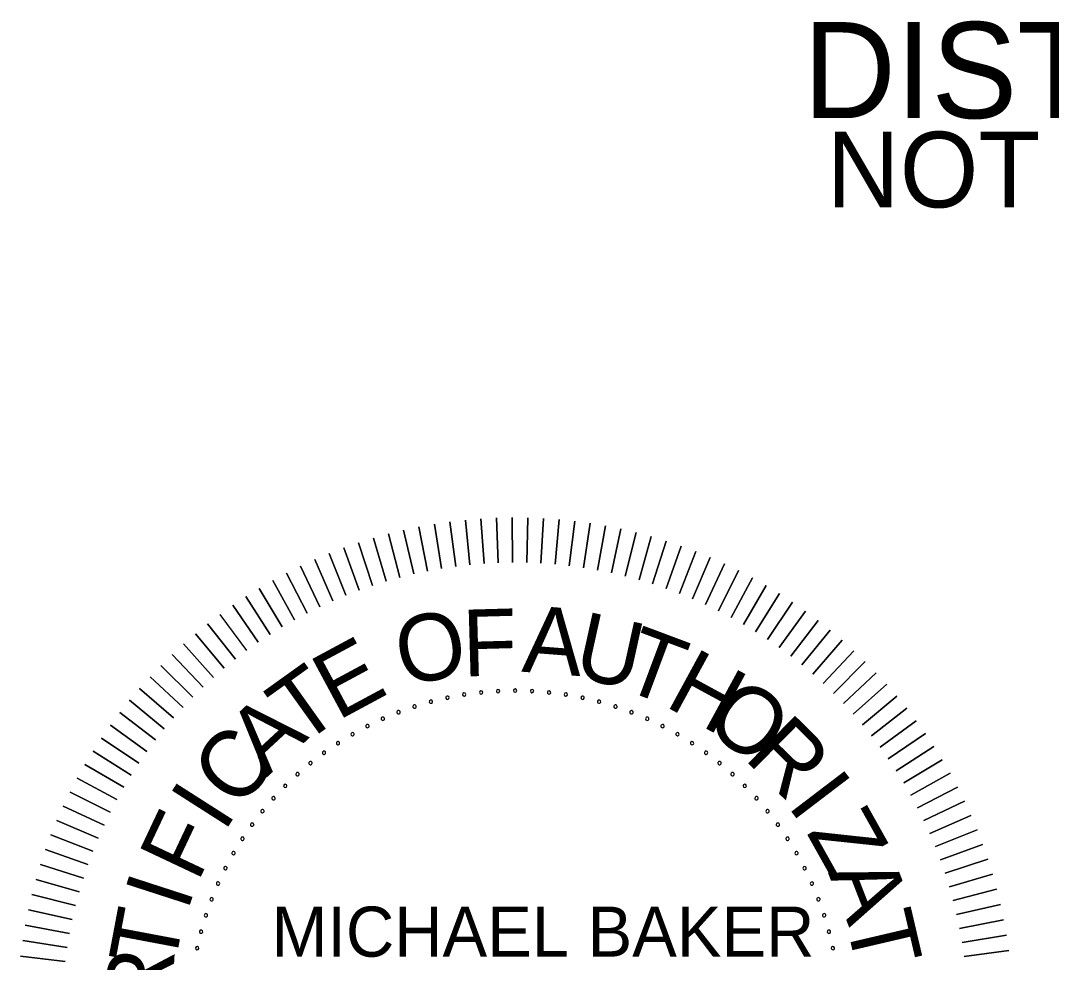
# Model space of a CAD drawing. Extents: x -31696 to 27919, y -8775 to 11152.
# Drawn here: x 10438 to 13014, y -5802 to -3450 of the extents above; entities that cross this region are included whole.
import ezdxf

# ---------------------------------------------------------------- set-up
doc = ezdxf.new("R2010")
doc.units = 0
for name, color, linetype in [('Level 2', 7, 'Continuous'), ('Level 47', 7, 'Continuous'), ('Level 48', 7, 'Continuous')]:
    doc.layers.add(name, color=color, linetype=linetype)

msp = doc.modelspace()

# ---------------------------------------------------------------- linework, layer by layer
at = {"layer": 'Level 47'}
for points in [[(11490, -4818.6), (11471.9, -4707.8)], [(11471.9, -4707.8), (11490, -4818.6)], [(11525.2, -4813.4), (11510.5, -4702.1)], [(11510.5, -4702.1), (11525.2, -4813.4)], [(11560.5, -4809.3), (11549.4, -4697.6)], [(11549.4, -4697.6), (11560.5, -4809.3)], [(11596, -4806.3), (11588.3, -4694.3)], [(11588.3, -4694.3), (11596, -4806.3)], [(11631.5, -4804.4), (11627.3, -4692.2)], [(11627.3, -4692.2), (11631.5, -4804.4)], [(11667.1, -4803.6), (11666.4, -4691.4)], [(11666.4, -4691.4), (11667.1, -4803.6)], [(11702.6, -4804), (11705.5, -4691.8)], [(11705.5, -4691.8), (11702.6, -4804)], [(11738.2, -4805.5), (11744.6, -4693.4)], [(11744.6, -4693.4), (11738.2, -4805.5)], [(11773.6, -4808.1), (11783.6, -4696.3)], [(11783.6, -4696.3), (11773.6, -4808.1)], [(11809, -4811.8), (11822.5, -4700.4)], [(11822.5, -4700.4), (11809, -4811.8)], [(11844.2, -4816.6), (11861.2, -4705.7)], [(11861.2, -4705.7), (11844.2, -4816.6)], [(11879.3, -4822.5), (11899.7, -4712.2)], [(11899.7, -4712.2), (11879.3, -4822.5)], [(11385.7, -4840.8), (11357.2, -4732.2)], [(11357.2, -4732.2), (11385.7, -4840.8)], [(11420.2, -4832.3), (11395.1, -4722.9)], [(11395.1, -4722.9), (11420.2, -4832.3)], [(11455, -4824.9), (11433.4, -4714.8)], [(11433.4, -4714.8), (11455, -4824.9)], [(11914.2, -4829.5), (11938.1, -4719.9)], [(11938.1, -4719.9), (11914.2, -4829.5)], [(11948.8, -4837.6), (11976.1, -4728.8)], [(11976.1, -4728.8), (11948.8, -4837.6)], [(11983.2, -4846.8), (12013.9, -4738.9)], [(12013.9, -4738.9), (11983.2, -4846.8)], [(11317.5, -4861), (11282.2, -4754.5)], [(11282.2, -4754.5), (11317.5, -4861)], [(11351.4, -4850.4), (11319.5, -4742.8)], [(11319.5, -4742.8), (11351.4, -4850.4)], [(12017.2, -4857.1), (12051.3, -4750.2)], [(12051.3, -4750.2), (12017.2, -4857.1)], [(12050.9, -4868.4), (12088.4, -4762.6)], [(12088.4, -4762.6), (12050.9, -4868.4)], [(11250.7, -4885.5), (11208.8, -4781.4)], [(11208.8, -4781.4), (11250.7, -4885.5)], [(11283.9, -4872.7), (11245.3, -4767.3)], [(11245.3, -4767.3), (11283.9, -4872.7)], [(12084.3, -4880.8), (12125, -4776.2)], [(12125, -4776.2), (12084.3, -4880.8)], [(11185.6, -4914.1), (11137.3, -4812.8)], [(11137.3, -4812.8), (11185.6, -4914.1)], [(11217.9, -4899.3), (11172.8, -4796.5)], [(11172.8, -4796.5), (11217.9, -4899.3)], [(12117.2, -4894.3), (12161.2, -4791)], [(12161.2, -4791), (12117.2, -4894.3)], [(12149.7, -4908.7), (12196.9, -4806.9)], [(12196.9, -4806.9), (12149.7, -4908.7)], [(11153.8, -4929.9), (11102.2, -4830.2)], [(11102.2, -4830.2), (11153.8, -4929.9)], [(12181.7, -4924.2), (12232.1, -4823.9)], [(12232.1, -4823.9), (12181.7, -4924.2)], [(12213.3, -4940.6), (12266.8, -4842)], [(12266.8, -4842), (12213.3, -4940.6)], [(11122.4, -4946.7), (11067.8, -4848.7)], [(11067.8, -4848.7), (11122.4, -4946.7)], [(12244.3, -4958.1), (12300.8, -4861.2)], [(12300.8, -4861.2), (12244.3, -4958.1)], [(11061.4, -4983.3), (11000.7, -4888.8)], [(11000.7, -4888.8), (11061.4, -4983.3)], [(11091.6, -4964.5), (11034, -4868.2)], [(11034, -4868.2), (11091.6, -4964.5)], [(12274.7, -4976.5), (12334.3, -4881.4)], [(12334.3, -4881.4), (12274.7, -4976.5)], [(11031.8, -5003), (10968.2, -4910.5)], [(10968.2, -4910.5), (11031.8, -5003)], [(12304.5, -4995.9), (12367.1, -4902.7)], [(12367.1, -4902.7), (12304.5, -4995.9)], [(11002.8, -5023.6), (10936.3, -4933.2)], [(12333.7, -5016.2), (12399.2, -4925)], [(12399.2, -4925), (12333.7, -5016.2)], [(10974.5, -5045.1), (10905.2, -4956.8)], [(10905.2, -4956.8), (10974.5, -5045.1)], [(12362.3, -5037.4), (12430.6, -4948.3)], [(12430.6, -4948.3), (12362.3, -5037.4)], [(10946.8, -5067.5), (10874.8, -4981.4)], [(10874.8, -4981.4), (10946.8, -5067.5)], [(12390.2, -5059.4), (12461.2, -4972.6)], [(12461.2, -4972.6), (12390.2, -5059.4)], [(10919.9, -5090.7), (10845.2, -5007)], [(10845.2, -5007), (10919.9, -5090.7)], [(12417.4, -5082.4), (12491.1, -4997.8)], [(12491.1, -4997.8), (12417.4, -5082.4)], [(10893.7, -5114.8), (10816.5, -5033.4)], [(10816.5, -5033.4), (10893.7, -5114.8)], [(12520.2, -5023.9), (12443.8, -5106.2)], [(12443.8, -5106.2), (12520.2, -5023.9)], [(10868.3, -5139.7), (10788.5, -5060.8)], [(10788.5, -5060.8), (10868.3, -5139.7)], [(12548.4, -5051), (12469.5, -5130.8)], [(12469.5, -5130.8), (12548.4, -5051)], [(10843.7, -5165.4), (10761.5, -5089)], [(10761.5, -5089), (10843.7, -5165.4)], [(12575.7, -5078.9), (12494.4, -5156.2)], [(12494.4, -5156.2), (12575.7, -5078.9)], [(10819.9, -5191.8), (10735.3, -5118.1)], [(10735.3, -5118.1), (10819.9, -5191.8)], [(12602.2, -5107.7), (12518.4, -5182.4)], [(12518.4, -5182.4), (12602.2, -5107.7)], [(10797, -5219), (10710.1, -5147.9)], [(10710.1, -5147.9), (10797, -5219)], [(12627.8, -5137.3), (12541.7, -5209.3)], [(12541.7, -5209.3), (12627.8, -5137.3)], [(12652.4, -5167.6), (12564.1, -5236.9)], [(12564.1, -5236.9), (12652.4, -5167.6)], [(10774.9, -5246.9), (10685.9, -5178.6)], [(10685.9, -5178.6), (10774.9, -5246.9)], [(12676, -5198.8), (12585.6, -5265.2)], [(12585.6, -5265.2), (12676, -5198.8)], [(10753.7, -5275.4), (10662.6, -5210)], [(10662.6, -5210), (10753.7, -5275.4)], [(10733.4, -5304.7), (10640.3, -5242.1)], [(10640.3, -5242.1), (10733.4, -5304.7)], [(12698.7, -5230.6), (12606.2, -5294.2)], [(12606.2, -5294.2), (12698.7, -5230.6)], [(10714.1, -5334.5), (10619, -5274.9)], [(10619, -5274.9), (10714.1, -5334.5)], [(12720.3, -5263.2), (12625.9, -5323.8)], [(12625.9, -5323.8), (12720.3, -5263.2)], [(12740.9, -5296.4), (12644.7, -5354.1)], [(12644.7, -5354.1), (12740.9, -5296.4)], [(10695.7, -5364.9), (10598.7, -5308.3)], [(10598.7, -5308.3), (10695.7, -5364.9)], [(12760.5, -5330.2), (12662.5, -5384.9)], [(12662.5, -5384.9), (12760.5, -5330.2)], [(10678.2, -5395.9), (10579.6, -5342.4)], [(10579.6, -5342.4), (10678.2, -5395.9)], [(10661.7, -5427.4), (10561.5, -5377)], [(10561.5, -5377), (10661.7, -5427.4)], [(12779, -5364.7), (12679.3, -5416.2)], [(12679.3, -5416.2), (12779, -5364.7)], [(12796.4, -5399.7), (12695.1, -5448)], [(12695.1, -5448), (12796.4, -5399.7)], [(10646.3, -5459.5), (10544.5, -5412.2)], [(10544.5, -5412.2), (10646.3, -5459.5)], [(10631.8, -5492), (10528.6, -5448)], [(10528.6, -5448), (10631.8, -5492)], [(12812.7, -5435.2), (12709.9, -5480.4)], [(12709.9, -5480.4), (12812.7, -5435.2)], [(10618.4, -5524.9), (10513.8, -5484.2)], [(10513.8, -5484.2), (10618.4, -5524.9)], [(12827.8, -5471.3), (12723.7, -5513.2)], [(12723.7, -5513.2), (12827.8, -5471.3)], [(12841.8, -5507.8), (12736.5, -5546.4)], [(12736.5, -5546.4), (12841.8, -5507.8)], [(10606, -5558.2), (10500.2, -5520.8)], [(10500.2, -5520.8), (10606, -5558.2)], [(10594.7, -5592), (10487.7, -5557.9)], [(10487.7, -5557.9), (10594.7, -5592)], [(12854.7, -5544.7), (12748.2, -5579.9)], [(12748.2, -5579.9), (12854.7, -5544.7)], [(12866.4, -5582), (12758.8, -5613.9)], [(12758.8, -5613.9), (12866.4, -5582)], [(10584.4, -5626), (10476.5, -5595.3)], [(10476.5, -5595.3), (10584.4, -5626)], [(10575.2, -5660.4), (10466.3, -5633.1)], [(10466.3, -5633.1), (10575.2, -5660.4)], [(12876.9, -5619.6), (12768.4, -5648.1)], [(12768.4, -5648.1), (12876.9, -5619.6)], [(12886.3, -5657.6), (12776.9, -5682.7)], [(12776.9, -5682.7), (12886.3, -5657.6)], [(10567.1, -5695), (10457.4, -5671.1)], [(10457.4, -5671.1), (10567.1, -5695)], [(10560.1, -5729.9), (10449.7, -5709.4)], [(10449.7, -5709.4), (10560.1, -5729.9)], [(12894.4, -5695.8), (12784.3, -5717.5)], [(12784.3, -5717.5), (12894.4, -5695.8)], [(12901.4, -5734.3), (12790.6, -5752.5)], [(12790.6, -5752.5), (12901.4, -5734.3)], [(10554.2, -5764.9), (10443.2, -5748)], [(10443.2, -5748), (10554.2, -5764.9)], [(10549.3, -5800.2), (10437.9, -5786.7)], [(10437.9, -5786.7), (10549.3, -5800.2)], [(12907.1, -5773), (12795.8, -5787.7)], [(12795.8, -5787.7), (12907.1, -5773)]]:
    msp.add_lwpolyline(points, dxfattribs=at)
for centre, start, end in [((11588.5, -5128.1), 6, 186), ((11630.9, -5124.8), 3, 183), ((11630.9, -5124.8), 183, 3), ((11673.4, -5123.7), 0, 180), ((11673.4, -5123.7), 180, 0), ((11715.9, -5124.8), 357, 177), ((11715.9, -5124.8), 177, 357), ((11758.3, -5128.1), 354, 174), ((11463.2, -5151.3), 15, 195), ((11463.2, -5151.3), 195, 15), ((11504.5, -5141.4), 12, 192), ((11504.5, -5141.4), 192, 12), ((11546.3, -5133.7), 9, 189), ((11546.3, -5133.7), 189, 9), ((11588.5, -5128.1), 186, 6), ((11758.3, -5128.1), 174, 354), ((11800.4, -5133.7), 171, 351), ((11800.4, -5133.7), 351, 171), ((11842.2, -5141.4), 348, 168), ((11842.2, -5141.4), 168, 348), ((11883.6, -5151.3), 165, 345), ((11883.6, -5151.3), 345, 165), ((11382.3, -5177.6), 21, 201), ((11382.3, -5177.6), 201, 21), ((11422.4, -5163.4), 18, 198), ((11422.4, -5163.4), 198, 18), ((11924.3, -5163.4), 162, 342), ((11924.3, -5163.4), 342, 162), ((11964.4, -5177.6), 159, 339), ((11964.4, -5177.6), 339, 159), ((11343, -5193.9), 24, 204), ((11343, -5193.9), 204, 24), ((12003.7, -5193.9), 156, 336), ((12003.7, -5193.9), 336, 156), ((11267.3, -5232.5), 30, 210), ((11304.7, -5212.2), 27, 207), ((11304.7, -5212.2), 207, 27), ((12042.1, -5212.2), 153, 333), ((12042.1, -5212.2), 333, 153), ((12079.4, -5232.5), 330, 150), ((11231, -5254.7), 33, 213), ((11231, -5254.7), 213, 33), ((11267.3, -5232.5), 210, 30), ((12079.4, -5232.5), 150, 330), ((12115.7, -5254.7), 147, 327), ((12115.7, -5254.7), 327, 147), ((11196, -5278.8), 36, 216), ((11196, -5278.8), 216, 36), ((12150.7, -5278.8), 144, 324), ((12150.7, -5278.8), 324, 144), ((11162.3, -5304.7), 39, 219), ((11162.3, -5304.7), 219, 39), ((12184.5, -5304.7), 141, 321), ((12184.5, -5304.7), 321, 141), ((11129.9, -5332.3), 42, 222), ((11129.9, -5332.3), 222, 42), ((12216.8, -5332.3), 138, 318), ((12216.8, -5332.3), 318, 138), ((11099.1, -5361.5), 45, 225), ((12247.6, -5361.5), 315, 135), ((11099.1, -5361.5), 225, 45), ((12247.6, -5361.5), 135, 315), ((11069.8, -5392.4), 48, 228), ((11069.8, -5392.4), 228, 48), ((12276.9, -5392.4), 132, 312), ((12276.9, -5392.4), 312, 132), ((11042.2, -5424.7), 51, 231), ((11042.2, -5424.7), 231, 51), ((12304.5, -5424.7), 129, 309), ((12304.5, -5424.7), 309, 129), ((11016.3, -5458.4), 54, 234), ((11016.3, -5458.4), 234, 54), ((12330.4, -5458.4), 126, 306), ((12330.4, -5458.4), 306, 126), ((10992.2, -5493.5), 57, 237), ((10992.2, -5493.5), 237, 57), ((12354.5, -5493.5), 123, 303), ((12354.5, -5493.5), 303, 123), ((10970, -5529.7), 60, 240), ((10970, -5529.7), 240, 60), ((12376.7, -5529.7), 120, 300), ((12376.7, -5529.7), 300, 120), ((10949.7, -5567.1), 63, 243), ((10949.7, -5567.1), 243, 63), ((12397, -5567.1), 117, 297), ((12397, -5567.1), 297, 117), ((10931.4, -5605.5), 66, 246), ((10931.4, -5605.5), 246, 66), ((12415.3, -5605.5), 114, 294), ((12415.3, -5605.5), 294, 114), ((10915.2, -5644.8), 69, 249), ((10915.2, -5644.8), 249, 69), ((12431.6, -5644.8), 111, 291), ((12431.6, -5644.8), 291, 111), ((10901, -5684.8), 72, 252), ((10901, -5684.8), 252, 72), ((12445.8, -5684.8), 108, 288), ((12445.8, -5684.8), 288, 108), ((10888.9, -5725.6), 75, 255), ((10888.9, -5725.6), 255, 75), ((12457.8, -5725.6), 105, 285), ((12457.8, -5725.6), 285, 105), ((10879, -5767), 78, 258), ((10879, -5767), 258, 78), ((12467.8, -5767), 102, 282), ((12467.8, -5767), 282, 102)]:
    msp.add_arc(centre, 4.17, start, end, dxfattribs=at)

# ---------------------------------------------------------------- texts
at = {"layer": 'Level 2'}
msp.add_text('NOT TO SCALE', height=189, dxfattribs=at).set_placement((12452.2, -3916.8))
at = {"layer": 'Level 47'}
for s, rotation, p in [('F', 1.5867, (11544, -5088.5)), ('A', 355.5955, (11688.5, -5076.2)), ('O', 10.7295, (11391.8, -5112.6)), ('U', 347.5481, (11814.6, -5088.1)), ('T', 339.5007, (11931, -5115.9)), ('E', 28.279, (11229.9, -5199.9)), ('H', 331.4533, (12044, -5160.5)), ('T', 35.5725, (11136.9, -5264.4)), ('O', 323.4059, (12139.7, -5213.2)), ('A', 42.8659, (11052.2, -5341.4)), ('R', 315.3585, (12243, -5292.2)), ('C', 50.1594, (10982.1, -5424.7)), ('I', 307.3112, (12351.4, -5409.6)), ('I', 57.4529, (10945.9, -5480.5)), ('F', 64.7464, (10880.5, -5605.1)), ('Z', 299.2638, (12400.3, -5477.6)), ('I', 72.0398, (10854.7, -5678.3)), ('A', 291.2164, (12455, -5577.8)), ('T', 79.3333, (10821.5, -5821.9)), ('T', 283.169, (12498.6, -5695.7)), ('R', 86.6268, (10813.9, -5932.1))]:
    msp.add_text(s, height=166.7, rotation=rotation, dxfattribs=at).set_placement(p)
msp.add_text('MICHAEL BAKER', height=125.016, dxfattribs=at).set_placement((11065.1, -5788.1))
at = {"layer": 'Level 48'}
msp.add_text('DISTRICT 1', height=240, dxfattribs=at).set_placement((12393.3, -3693.8))

doc.saveas('drawing.dxf')
